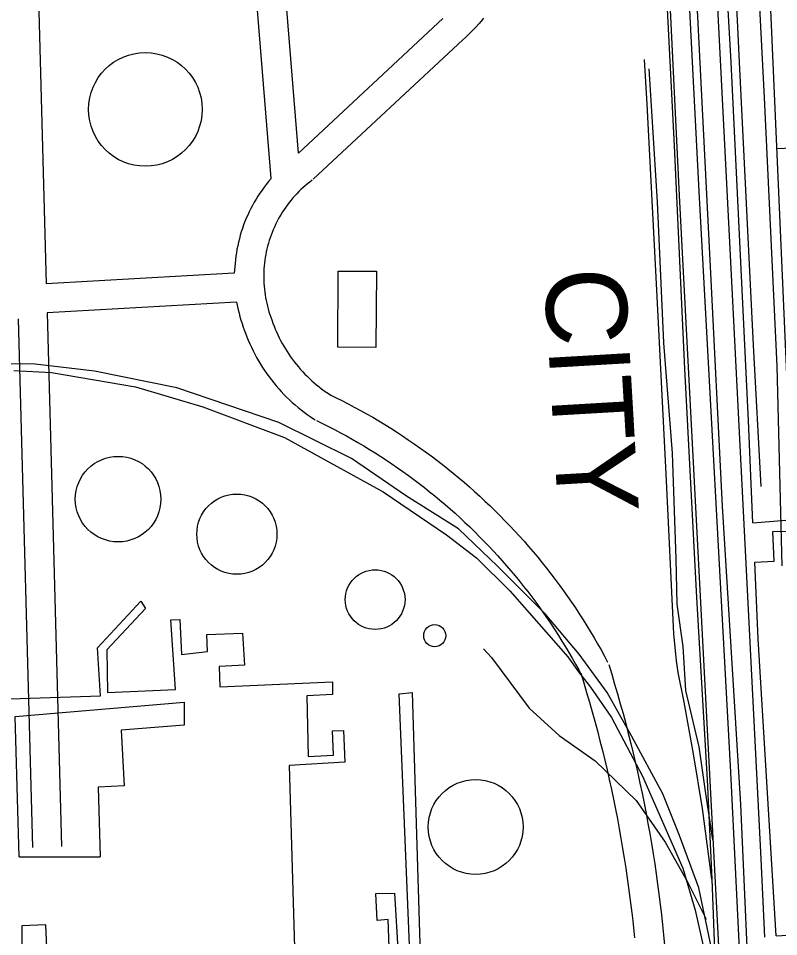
# Model space of a CAD drawing. Extents: x 3313447 to 3351316, y 703786 to 729172.
# Drawn here: x 3329508 to 3330288, y 722771 to 723714 of the extents above; entities that cross this region are included whole.
import ezdxf

# ---------------------------------------------------------------- set-up
doc = ezdxf.new("R2010")
doc.units = 0
for name, color, linetype in [('V-BLDG-OTLN', 7, 'Continuous'), ('V-DOMW-TANK', 7, 'Continuous'), ('V-RAIL-IDEN', 7, 'Continuous'), ('V-RAIL-TRAK', 7, 'Continuous'), ('V-ROAD-CNTR', 7, 'Continuous'), ('V-UTIL-LINE', 7, 'Continuous')]:
    doc.layers.add(name, color=color, linetype=linetype)

msp = doc.modelspace()

# ---------------------------------------------------------------- linework, layer by layer
at = {"layer": 'V-BLDG-OTLN'}
msp.add_lwpolyline([(3329875.44, 723454.24), (3329875.06, 723376.2), (3329835.96, 723376.39), (3329836.34, 723454.43)], close=True, dxfattribs=at)
at = {"layer": 'V-DOMW-TANK'}
for centre, radius in [((3329638.33, 723620.44), 58.33), ((3329610.3, 723220.39), 43.91), ((3329732.25, 723184.43), 41.15), ((3329874.19, 723117.24), 30.66), ((3329935.36, 723080.23), 11.32), ((3329977.37, 722883.83), 48.7)]:
    msp.add_circle(centre, radius, dxfattribs=at)
at = {"layer": 'V-RAIL-TRAK'}
for points in [[(3330131.51, 724591.27), (3330139.3, 724420.34), (3330148.6, 724227.22), (3330158.98, 724024.75), (3330170.18, 723797.31), (3330181.32, 723583.04), (3330191.83, 723354.21), (3330204.11, 723119.49), (3330215.11, 722932.28), (3330219.78, 722830.34), (3330226.08, 722666.56)], [(3330325.96, 721424.85), (3330317.7, 721591.28), (3330310.53, 721734.46), (3330298.81, 721926.52), (3330289.77, 722138.37), (3330273.04, 722431.67), (3330260.4, 722668.12), (3330249.49, 722907.01), (3330230.96, 723213.27), (3330218.24, 723465.67), (3330204.02, 723743.03), (3330189.87, 724004.79), (3330176.48, 724253.03), (3330165.32, 724472.14), (3330161.1, 724585.96)], [(3330165.32, 724472.14), (3330174.66, 724408.03), (3330178.94, 724385.86), (3330185.31, 724359.54), (3330197.65, 724319.72), (3330216.65, 724266.06), (3330233.55, 724215.51), (3330240.64, 724183.64), (3330251.21, 724081.39), (3330262.05, 723857.77), (3330273.58, 723632.76), (3330286.42, 723356.77), (3330291.61, 723151.84)], [(3330270.39, 723233.23), (3330262.73, 723378.5), (3330248.43, 723669.04), (3330236.42, 723919.71), (3330224.83, 724155.13), (3330220.82, 724193.95), (3330215.09, 724231.03), (3330205.47, 724280.92), (3330197.65, 724319.72)], [(3330219.78, 722830.34), (3330210.4, 722902.78), (3330201.1, 722958.91), (3330191.47, 723011.92), (3330185.42, 723042.41), (3330183.63, 723054.54), (3330180.71, 723082.27), (3330172.95, 723246.26), (3330163.33, 723434.87), (3330153.36, 723625.91), (3330150.7, 723671.67)], [(3329503.38, 723352.35), (3329541.89, 723350.46), (3329628.31, 723335.64), (3329697.42, 723315.18), (3329781.16, 723283.7), (3329882.36, 723228.02), (3329947.43, 723183.61), (3329978.41, 723160.19), (3330012.57, 723126.37), (3330071.87, 723058.35), (3330082.99, 723043.15), (3330095.26, 723027.26), (3330116.91, 722996.16), (3330148.77, 722935.97), (3330190.17, 722841.51), (3330202.88, 722798.57), (3330215.65, 722740.72)]]:
    msp.add_lwpolyline(points, dxfattribs=at)
at = {"layer": 'V-ROAD-CNTR'}
msp.add_line((3330286.58, 723580.25), (3330316.55, 723581.57), dxfattribs=at)
for points in [[(3330000.91, 727371.92), (3330011.6, 727012.1), (3330035.19, 726652.61), (3330064.89, 725878.16), (3330103.94, 725200.09), (3330125.11, 724765.21), (3330141.94, 724403.2), (3330158.81, 724097.31), (3330186.32, 723532.09), (3330236.42, 722578.67), (3330273.8, 721897.85), (3330314.54, 721094.9), (3330366.69, 720142.98), (3330425.82, 719049.43), (3330444.1, 718741.02)], [(3330466.89, 718738.22), (3330443.32, 719091.62), (3330425.08, 719389.43), (3330397.62, 719905.26), (3330375.78, 720281.88), (3330354.72, 720674.11), (3330332.36, 721137.75), (3330309.12, 721591.09), (3330299.17, 721854.13), (3330279.29, 722188.18), (3330255.73, 722605.27), (3330239.52, 722940.11), (3330206.77, 723536.19), (3330170.59, 724242.04), (3330145.9, 724754.04), (3330120.45, 725277.02), (3330081.85, 725930.58), (3330062.27, 726434.21), (3330049.61, 726666.15), (3330008.55, 727333.21), (3330005.38, 727371.93)], [(3330311.5, 723140.73), (3330307.03, 723143.82), (3330304.65, 723168.89), (3330249.47, 724424.72), (3330266.96, 724478.51), (3330301.52, 724518.43), (3330340.4, 724569.48), (3330422.66, 724691.21), (3330465.59, 724717.93), (3330499.22, 724735.06), (3330542.79, 724749.3), (3330572.05, 724746.91), (3331393.69, 724672.84)], [(3329795.35, 723575.55), (3329749.35, 724145.08)], [(3329767.35, 723549.59), (3329748.6, 723781.68)], [(3329527.58, 723772.28), (3329536.58, 723441.53)], [(3329943.72, 723713.76), (3329795.35, 723575.55)], [(3329985.52, 723714.23), (3329983.04, 723711.19), (3329980.5, 723708.21), (3329977.89, 723705.28), (3329975.22, 723702.42), (3329972.49, 723699.61), (3329969.69, 723696.87), (3329966.83, 723694.19), (3329963.96, 723691.62), (3329963.81, 723691.48)], [(3329964.17, 723691.8), (3329810.6, 723548.76)], [(3330155.13, 723662.05), (3330163.6, 723525.68), (3330170.11, 723380.94), (3330179.01, 723267.59), (3330182.75, 723158.96), (3330184.01, 723112.52), (3330190.21, 723069.16), (3330192.65, 723024.01), (3330206.68, 722966.05), (3330213.44, 722918.26), (3330220.45, 722870.61)], [(3329767.36, 723549.45), (3329764.77, 723546.38), (3329762.46, 723543.51), (3329760.22, 723540.58), (3329758.05, 723537.6), (3329755.95, 723534.57), (3329753.93, 723531.48), (3329751.98, 723528.35), (3329750.11, 723525.18), (3329748.31, 723521.96), (3329746.59, 723518.7), (3329744.95, 723515.4), (3329743.39, 723512.05), (3329741.91, 723508.68), (3329740.51, 723505.26), (3329739.2, 723501.82), (3329737.97, 723498.34), (3329736.82, 723494.84), (3329735.76, 723491.31), (3329734.78, 723487.75), (3329733.88, 723484.18), (3329733.08, 723480.58), (3329732.36, 723476.96), (3329731.73, 723473.33), (3329731.18, 723469.68), (3329730.73, 723466.03), (3329730.36, 723462.35), (3329729.61, 723452.51)], [(3329809.49, 723547.82), (3329806.99, 723545.91), (3329804.68, 723544.05), (3329802.41, 723542.14), (3329800.19, 723540.17), (3329798.02, 723538.15), (3329795.9, 723536.08), (3329793.82, 723533.96), (3329791.8, 723531.78), (3329789.84, 723529.57), (3329787.92, 723527.3), (3329786.06, 723524.99), (3329784.26, 723522.63), (3329782.52, 723520.24), (3329780.83, 723517.8), (3329779.2, 723515.32), (3329777.63, 723512.8), (3329776.13, 723510.24), (3329774.68, 723507.66), (3329773.3, 723505.03), (3329771.98, 723502.38), (3329770.73, 723499.69), (3329769.54, 723496.97), (3329768.41, 723494.23), (3329767.35, 723491.46), (3329766.36, 723488.66), (3329765.44, 723485.85), (3329764.59, 723483), (3329763.8, 723480.14), (3329763.08, 723477.27), (3329762.43, 723474.37), (3329761.85, 723471.46), (3329761.35, 723468.54), (3329760.91, 723465.61), (3329760.54, 723462.67), (3329760.24, 723459.72), (3329760.02, 723456.76), (3329759.86, 723453.79), (3329759.78, 723450.83), (3329759.77, 723447.87), (3329759.83, 723444.9), (3329759.96, 723441.94), (3329760.16, 723438.98), (3329760.44, 723436.03), (3329760.78, 723433.08), (3329761.2, 723430.14), (3329761.68, 723427.22), (3329762.24, 723424.31), (3329762.86, 723421.41), (3329763.56, 723418.52), (3329764.32, 723415.66), (3329765.15, 723412.81), (3329766.05, 723409.99), (3329767.03, 723407.17), (3329768, 723404.56)], [(3329729.61, 723452.51), (3329536.58, 723441.53)], [(3329731.72, 723422.58), (3329537.39, 723411.52)], [(3329731.92, 723422.59), (3329733.61, 723414.73), (3329734.48, 723411.14), (3329735.43, 723407.58), (3329736.46, 723404.04), (3329737.58, 723400.53), (3329738.78, 723397.05), (3329739.87, 723394.11)], [(3329507.55, 723405.4), (3329522.3, 722862.91)], [(3329537.39, 723411.52), (3329552.29, 722863.72)], [(3329768.08, 723404.32), (3329769.23, 723401.08), (3329770.38, 723398.02), (3329771.61, 723394.98), (3329772.9, 723391.97), (3329774.26, 723388.99), (3329775.68, 723386.05), (3329777.17, 723383.13), (3329778.72, 723380.25), (3329780.34, 723377.4), (3329782.02, 723374.59), (3329783.76, 723371.82), (3329785.56, 723369.08), (3329787.43, 723366.39), (3329789.35, 723363.74), (3329791.33, 723361.13), (3329793.36, 723358.57), (3329795.46, 723356.05), (3329797.61, 723353.58), (3329799.81, 723351.16), (3329802.07, 723348.79), (3329804.38, 723346.47), (3329806.74, 723344.2), (3329809.15, 723341.98), (3329811.6, 723339.82), (3329814.11, 723337.71), (3329816.66, 723335.66), (3329819.26, 723333.66), (3329821.9, 723331.73), (3329824.58, 723329.85), (3329827.34, 723328.01), (3329828.76, 723327.09)], [(3329739.79, 723394.35), (3329741.04, 723390.79), (3329742.44, 723387.1), (3329743.91, 723383.45), (3329745.46, 723379.83), (3329747.1, 723376.25), (3329748.81, 723372.7), (3329750.6, 723369.19), (3329752.47, 723365.72), (3329754.42, 723362.3), (3329756.44, 723358.91), (3329758.53, 723355.58), (3329760.7, 723352.29), (3329762.94, 723349.05), (3329765.26, 723345.86), (3329767.64, 723342.72), (3329770.09, 723339.64), (3329772.61, 723336.61), (3329775.19, 723333.64), (3329777.85, 723330.72), (3329780.56, 723327.87), (3329783.34, 723325.08), (3329786.18, 723322.35), (3329789.08, 723319.68), (3329792.03, 723317.08), (3329795.05, 723314.54), (3329798.12, 723312.07), (3329801.24, 723309.67), (3329804.42, 723307.34), (3329807.65, 723305.08), (3329810.89, 723302.92), (3329812.52, 723301.87)], [(3330229.78, 722704.96), (3330226.77, 722725.11), (3330206.5, 722821.37), (3330186.61, 722875.12), (3330169.69, 722917.86), (3330137.68, 722976.86), (3330112.49, 723021.95), (3330083.62, 723061.18), (3330048.7, 723102.74), (3329999.98, 723151.45), (3329959.89, 723189.79), (3329906.53, 723223.58), (3329849.87, 723262.16), (3329775.47, 723299.06), (3329670.47, 723334.68), (3329586.22, 723351.84), (3329525.31, 723358.94), (3329412.13, 723359.94)], [(3329827.21, 723327.96), (3329833.61, 723324.85), (3329840.05, 723321.62), (3329846.45, 723318.32), (3329852.81, 723314.94), (3329859.14, 723311.5), (3329865.43, 723307.98), (3329871.67, 723304.39), (3329877.88, 723300.73), (3329884.04, 723297), (3329890.16, 723293.2), (3329896.24, 723289.33), (3329902.27, 723285.39), (3329908.26, 723281.38), (3329914.2, 723277.3), (3329920.09, 723273.16), (3329925.94, 723268.95), (3329931.74, 723264.68), (3329937.49, 723260.34), (3329943.19, 723255.93), (3329948.84, 723251.46), (3329954.44, 723246.93), (3329959.99, 723242.33), (3329965.48, 723237.67), (3329970.92, 723232.94), (3329976.3, 723228.16), (3329981.64, 723223.31), (3329986.91, 723218.41), (3329992.13, 723213.44), (3329997.29, 723208.42), (3330002.4, 723203.33), (3330007.45, 723198.19), (3330012.44, 723193), (3330017.36, 723187.74), (3330022.23, 723182.43), (3330027.04, 723177.07), (3330031.79, 723171.65), (3330036.48, 723166.17), (3330041.1, 723160.65), (3330045.66, 723155.07), (3330050.15, 723149.44), (3330054.58, 723143.76), (3330058.95, 723138.03), (3330063.25, 723132.25), (3330067.49, 723126.42), (3330071.66, 723120.55), (3330075.76, 723114.62), (3330079.79, 723108.65), (3330083.76, 723102.64), (3330087.65, 723096.58), (3330091.48, 723090.48), (3330095.24, 723084.33), (3330098.93, 723078.14), (3330102.54, 723071.91), (3330106.09, 723065.64), (3330109.56, 723059.33), (3330112.86, 723053.18)], [(3329814.07, 723301), (3329820.31, 723297.95), (3329826.45, 723294.88), (3329832.55, 723291.73), (3329838.61, 723288.52), (3329844.64, 723285.23), (3329850.63, 723281.88), (3329856.58, 723278.46), (3329862.49, 723274.97), (3329868.36, 723271.42), (3329874.19, 723267.8), (3329879.98, 723264.11), (3329885.73, 723260.36), (3329891.43, 723256.54), (3329897.09, 723252.66), (3329902.71, 723248.71), (3329908.28, 723244.7), (3329913.8, 723240.63), (3329919.28, 723236.5), (3329924.71, 723232.3), (3329930.09, 723228.04), (3329935.42, 723223.72), (3329940.71, 723219.34), (3329945.94, 723214.9), (3329951.12, 723210.4), (3329956.25, 723205.84), (3329961.33, 723201.23), (3329966.36, 723196.55), (3329971.33, 723191.82), (3329976.25, 723187.04), (3329981.11, 723182.19), (3329985.92, 723177.3), (3329990.67, 723172.35), (3329995.37, 723167.34), (3330000.01, 723162.28), (3330004.59, 723157.17), (3330009.11, 723152.01), (3330013.57, 723146.79), (3330017.98, 723141.53), (3330022.32, 723136.22), (3330026.6, 723130.85), (3330030.83, 723125.44), (3330034.98, 723119.98), (3330039.08, 723114.48), (3330043.12, 723108.92), (3330047.09, 723103.33), (3330050.99, 723097.68), (3330054.84, 723092), (3330058.62, 723086.27), (3330062.33, 723080.5), (3330065.97, 723074.68), (3330069.55, 723068.83), (3330073.07, 723062.93), (3330076.51, 723056.99), (3330079.89, 723051.02), (3330083.2, 723045.01), (3330086.42, 723039)], [(3329985.44, 723066.57), (3329993.76, 723057.81), (3330032.37, 723005.67), (3330063.07, 722977.89), (3330100.13, 722951.77), (3330142.18, 722911.04), (3330172.08, 722868.27), (3330194.85, 722827.52), (3330213.98, 722789.08)], [(3330113.97, 723050.53), (3330117.06, 723040.55), (3330120.09, 723030.48), (3330123.04, 723020.4), (3330125.91, 723010.3), (3330128.71, 723000.17), (3330131.43, 722990.02), (3330134.07, 722979.85), (3330136.63, 722969.66), (3330139.11, 722959.45), (3330141.52, 722949.23), (3330143.84, 722938.98), (3330146.09, 722928.72), (3330148.26, 722918.44), (3330150.35, 722908.14), (3330152.35, 722897.83), (3330154.28, 722887.5), (3330156.13, 722877.16), (3330157.9, 722866.8), (3330159.59, 722856.43), (3330161.21, 722846.05), (3330162.74, 722835.66), (3330164.19, 722825.25), (3330165.56, 722814.83), (3330166.85, 722804.41), (3330168.06, 722793.97), (3330169.19, 722783.53), (3330170.24, 722773.07), (3330171.2, 722762.62)], [(3330085.31, 723041.65), (3330088.37, 723031.78), (3330091.33, 723021.95), (3330094.22, 723012.08), (3330097.03, 723002.2), (3330099.76, 722992.3), (3330102.42, 722982.37), (3330105, 722972.43), (3330107.51, 722962.46), (3330109.94, 722952.48), (3330112.29, 722942.47), (3330114.56, 722932.45), (3330116.76, 722922.42), (3330118.88, 722912.36), (3330120.92, 722902.29), (3330122.89, 722892.21), (3330124.77, 722882.1), (3330126.58, 722871.99), (3330128.31, 722861.86), (3330129.97, 722851.72), (3330131.54, 722841.56), (3330133.04, 722831.4), (3330134.46, 722821.22), (3330135.8, 722811.03), (3330137.06, 722800.84), (3330138.24, 722790.63), (3330139.35, 722780.41), (3330140.37, 722770.19)]]:
    msp.add_lwpolyline(points, dxfattribs=at)
at = {"layer": 'V-UTIL-LINE'}
for p, q in [((3329508.63, 722853.21), (3329592.06, 722853.28)), ((3329535.98, 722783.41), (3329511.41, 722782.25))]:
    msp.add_line(p, q, dxfattribs=at)
for points in [[(3330184.69, 724503.2), (3330185.32, 724490.19), (3330191.35, 724387.62), (3330230.54, 724261.81), (3330234.69, 724258.39), (3330237.55, 724237.06), (3330199.2, 724194.86), (3330218.04, 723872.71), (3330240.16, 723443.85), (3330270, 722851.15), (3330274.04, 722770.56)], [(3330262.11, 723196.2), (3330338.11, 723202.2), (3330334.52, 723296.01), (3330343.17, 723296.74), (3330340.45, 723356.28), (3330347.37, 723357), (3330359.77, 723162.15), (3330632.52, 723175.29), (3330590.35, 724125.07), (3330550.54, 724122.44), (3330560.89, 723925.16), (3330530.08, 723923.62), (3330533.46, 723871.7), (3330469.77, 723868.27), (3330466.35, 723930.22), (3330423.08, 723928.27), (3330416.28, 724041.1), (3330344.64, 724036.93), (3330340.85, 724103.04), (3330303.47, 724100.08), (3330304.11, 724109.78), (3330245.65, 724100.83), (3330245.77, 724076.25)], [(3330262.11, 723196.2), (3330257.41, 723300.72), (3330239.72, 723669.01), (3330216.79, 724070.18)], [(3330263.94, 723155.74), (3330283.98, 723156.58), (3330282.44, 723187.04), (3330341.64, 723188.37)], [(3330285.86, 722771.98), (3330653.82, 722794.23), (3330651.54, 722835.07), (3330391.59, 722824.76), (3330390.35, 722865.96), (3330419.77, 722866.1), (3330421.65, 722837.03), (3330547.97, 722844.59), (3330537.16, 722998.95), (3330549.62, 722999.35), (3330556.62, 722846.37), (3330651.46, 722850.65), (3330636.41, 723158.01), (3330344.97, 723145.11), (3330341.64, 723188.37)], [(3330285.86, 722771.98), (3330267.48, 723076.99), (3330263.94, 723155.74)], [(3329499.5, 723015.53), (3329592.27, 723018.42), (3329589.25, 723067.57), (3329633.67, 723115.57), (3329638.56, 723107.98), (3329598.61, 723065.54), (3329599.52, 723021.92), (3329669.09, 723025.04), (3329664.58, 723096.34), (3329673.58, 723096.73), (3329675.49, 723060.73), (3329702.14, 723063.98), (3329701.35, 723081.29), (3329738.04, 723082.86), (3329739.94, 723049.98), (3329713.98, 723048.46), (3329714.78, 723027.7), (3329830.39, 723032.78), (3329830.45, 723019.97), (3329804.15, 723018.45), (3329805.5, 722956.14), (3329831.46, 722957.66), (3329830.29, 722982.58), (3329841.72, 722982.98), (3329842.92, 722950.44), (3329785.81, 722947.04), (3329791.66, 722748)], [(3329909.68, 722754.14), (3329899, 723020.66), (3329912.15, 723021.76), (3329920.42, 722752.8)], [(3329508.63, 722853.21), (3329504.79, 722997.21), (3329678.16, 723011.93), (3329678.28, 722988.39), (3329613.56, 722983.22), (3329616.62, 722926.11), (3329589.97, 722924.59), (3329592.06, 722853.28)], [(3329888.93, 722750.92), (3329887.7, 722788.99), (3329876.28, 722787.9), (3329874.75, 722815.58), (3329894.14, 722816.03), (3329897.92, 722753.04)], [(3329511.41, 722782.25), (3329511.96, 722741.4), (3329547.26, 722743.31), (3329547.22, 722752.66), (3329537.52, 722752.26), (3329535.98, 722783.41)]]:
    msp.add_lwpolyline(points, dxfattribs=at)

# ---------------------------------------------------------------- texts
at = {"layer": 'V-RAIL-IDEN'}
msp.add_text('CITY', height=83, rotation=273.34863, dxfattribs=at).set_placement((3330047.45, 723455.72))

doc.saveas('drawing.dxf')
